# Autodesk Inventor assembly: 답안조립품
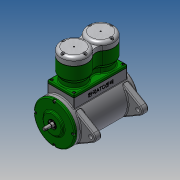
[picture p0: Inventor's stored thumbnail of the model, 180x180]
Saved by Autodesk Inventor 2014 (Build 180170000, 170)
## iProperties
Created: 2019-08
Part Number: 답안조립품
Document SubType Name: Assembly
Designer: kb542
Mass: 7629.46 g
Surface Area: 5241.59 cm^2
Volume: 2149.39 cm^3
Density: 3.5496 g/cm^3
Author: kb542
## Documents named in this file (18)
- C:\Users\kb542\Desktop\390804V1016\답안조립품.iam
- C:\Users\kb542\Desktop\390804V1016\본체.ipt
- C:\Users\kb542\Desktop\390804V1016\크랭크축.ipt
- C:\Users\kb542\Desktop\390804V1016\베어링 12 x 28 x 8.ipt
- C:\Users\kb542\Desktop\390804V1016\앞커버.ipt
- C:\Users\kb542\Desktop\390804V1016\오일 실 12 25 7.ipt
- C:\Users\kb542\Desktop\390804V1016\볼트 M4 x 8.ipt
- C:\Users\kb542\Desktop\390804V1016\실린더 개스킷.ipt
- C:\Users\kb542\Desktop\390804V1016\실린더.ipt
- C:\Users\kb542\Desktop\390804V1016\실린더헤드 개스킷.ipt
- C:\Users\kb542\Desktop\390804V1016\실린더헤드.ipt
- C:\Users\kb542\Desktop\390804V1016\볼트 M5 x 20.ipt
- C:\Users\kb542\Desktop\390804V1016\커넥팅로드.ipt
- C:\Users\kb542\Desktop\390804V1016\커넥팅로드 엔드.ipt
- C:\Users\kb542\Desktop\390804V1016\피스톤.ipt
- C:\Users\kb542\Desktop\390804V1016\육각 머리 볼트 M4 x 16.ipt
- C:\Users\kb542\Desktop\390804V1016\너트 M4.ipt
- C:\Users\kb542\Desktop\390804V1016\피스톤핀.ipt
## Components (4 placed, 2 different names)
1. 피스톤:1 — 플러쉬:1
2. 피스톤핀:1
3. 피스톤:2 — 플러쉬:2
4. 피스톤핀:2
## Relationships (2: Flush 2)
- 플러쉬:1 [Flush]: 피스톤:1
- 플러쉬:2 [Flush]: 피스톤:2
